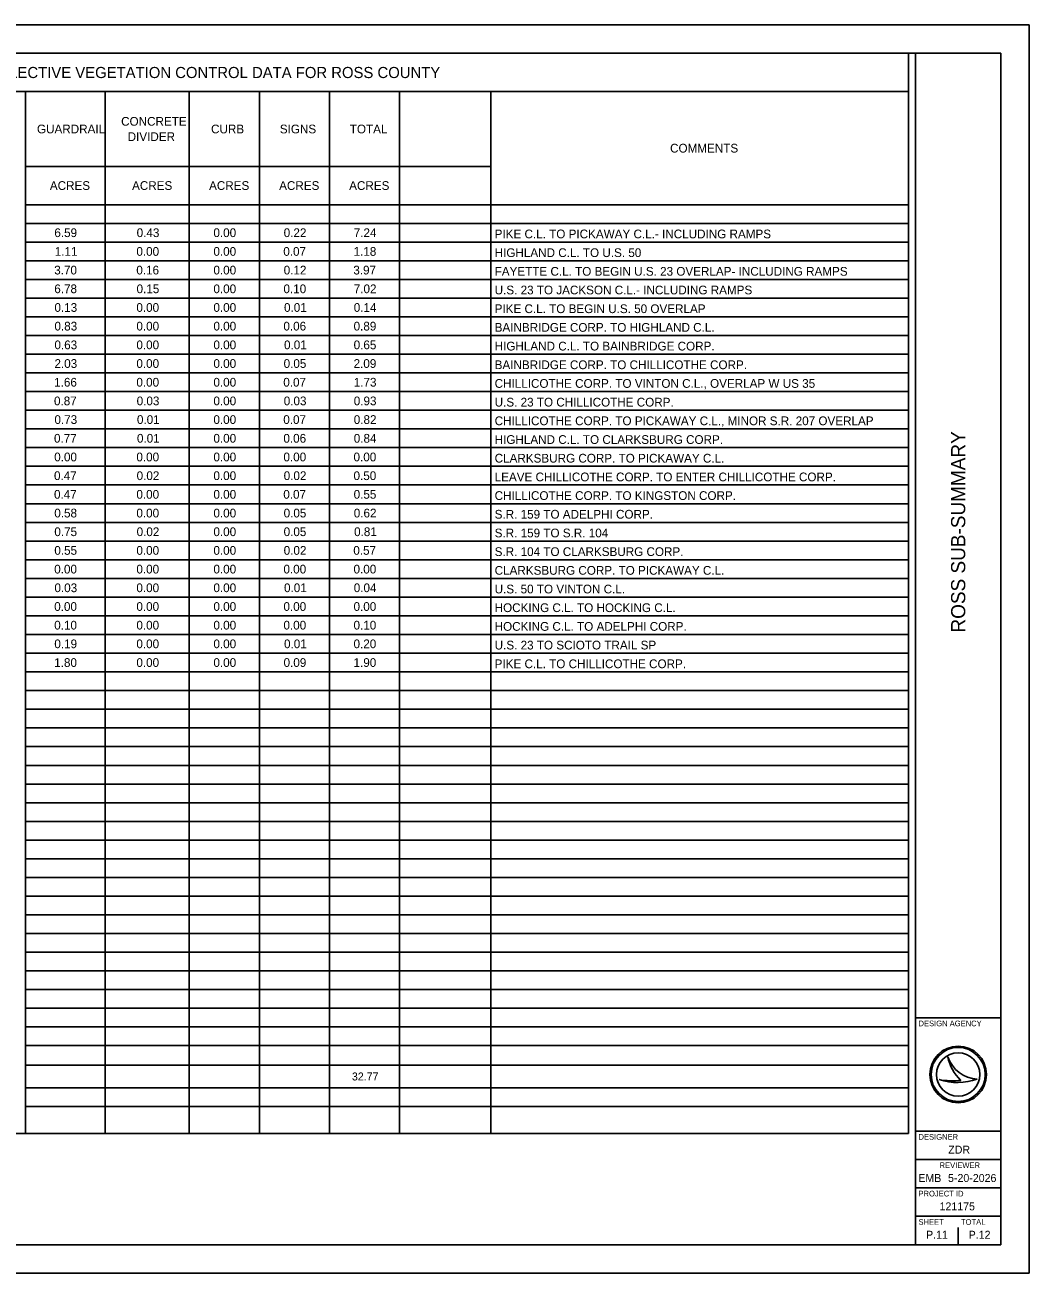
# Model space of a CAD drawing. Extents: x 0 to 34, y 0 to 22.
# Drawn here: x 16.29 to 34, y 0 to 22 of the extents above; entities that cross this region are included whole.
import ezdxf

# ---------------------------------------------------------------- set-up
doc = ezdxf.new("R2010")
doc.units = 0
for name, color, linetype in [('SH_Border', 7, 'Continuous'), ('SH_Cut_Line', 7, 'Continuous'), ('SH_Data', 7, 'Continuous'), ('SH_Text', 7, 'Continuous')]:
    doc.layers.add(name, color=color, linetype=linetype)

msp = doc.modelspace()

# ---------------------------------------------------------------- linework, layer by layer
at = {"layer": 'SH_Border'}
for p, q in [((32, 0.5), (32, 21.5)), ((32, 4.5), (33.5, 4.5)), ((32, 2.5), (33.5, 2.5)), ((32, 2), (33.5, 2)), ((32, 1.5), (33.5, 1.5)), ((32, 1), (33.5, 1))]:
    msp.add_line(p, q, dxfattribs=at)
msp.add_lwpolyline([(1.5, 21.5), (33.5, 21.5), (33.5, 0.5), (1.5, 0.5)], close=True, dxfattribs=at)
at = {"layer": 'SH_Cut_Line'}
msp.add_lwpolyline([(0, 0), (34, 0), (34, 22), (0, 22)], close=True, dxfattribs=at)
at = {"layer": 'SH_Data'}
for p, q in [((32.567, 3.81), (32.567, 3.81)), ((32.417, 3.41), (32.417, 3.41)), ((32.75, 3.5), (32.75, 3.5)), ((33.087, 3.419), (33.087, 3.419)), ((32.375, 0.675), (32.375, 0.675)), ((32.75, 0.5), (32.75, 0.8))]:
    msp.add_line(p, q, dxfattribs=at)
for radius in [0.5, 0.477, 0.477, 0.382]:
    msp.add_circle((32.75, 3.5), radius, dxfattribs=at)
for centre, radius, start, end in [((33.116, 3.998), 0.58, 198.9257, 198.9319), ((33.347, 3.97), 0.796, 191.6379, 191.6421), ((33.116, 3.998), 0.58, 198.9319, 267.1657), ((33.347, 3.97), 0.796, 191.6421, 226.0947), ((32.739, 4.37), 1.013, 251.4576, 290.0832), ((32.648, 4.654), 1.266, 259.4964, 259.4995), ((32.739, 4.37), 1.013, 251.4527, 251.4576), ((32.648, 4.654), 1.266, 259.4995, 276.6672)]:
    msp.add_arc(centre, radius, start, end, dxfattribs=at)
at = {"layer": 'SH_Text'}
for p, q in [((1.5, 21.5), (31.872, 21.5)), ((31.872, 21.5), (31.872, 2.46)), ((7.451, 20.825), (16.302, 20.825)), ((16.28, 20.825), (31.872, 20.825)), ((16.302, 20.825), (16.302, 2.46)), ((17.707, 20.825), (17.707, 2.46)), ((19.189, 20.825), (19.189, 2.46)), ((20.425, 20.825), (20.425, 2.46)), ((21.66, 20.825), (21.66, 2.46)), ((22.895, 20.825), (22.895, 2.46)), ((24.509, 20.825), (24.509, 2.46)), ((16.302, 19.507), (24.509, 19.507)), ((16.302, 18.832), (31.872, 18.832)), ((16.302, 18.502), (31.872, 18.502)), ((16.302, 18.173), (31.872, 18.173)), ((16.302, 17.844), (31.872, 17.844)), ((16.302, 17.514), (31.872, 17.514)), ((16.302, 17.185), (31.872, 17.185)), ((16.302, 16.855), (31.872, 16.855)), ((16.302, 16.526), (31.872, 16.526)), ((16.302, 16.196), (31.872, 16.196)), ((16.302, 15.867), (31.872, 15.867)), ((16.302, 15.538), (31.872, 15.538)), ((16.302, 15.208), (31.872, 15.208)), ((16.302, 14.879), (31.872, 14.879)), ((16.302, 14.549), (31.872, 14.549)), ((16.302, 14.22), (31.872, 14.22)), ((16.302, 13.891), (31.872, 13.891)), ((16.302, 13.561), (31.872, 13.561)), ((16.302, 13.232), (31.872, 13.232)), ((16.302, 12.902), (31.872, 12.902)), ((16.302, 12.573), (31.872, 12.573)), ((16.302, 12.244), (31.872, 12.244)), ((16.302, 11.914), (31.872, 11.914)), ((16.302, 11.585), (31.872, 11.585)), ((16.302, 11.255), (31.872, 11.255)), ((16.302, 10.926), (31.872, 10.926)), ((16.302, 10.596), (31.872, 10.596)), ((16.302, 10.267), (31.872, 10.267)), ((16.302, 9.938), (31.872, 9.938)), ((16.302, 9.608), (31.872, 9.608)), ((16.302, 9.279), (31.872, 9.279)), ((16.302, 8.949), (31.872, 8.949)), ((16.302, 8.62), (31.872, 8.62)), ((16.302, 8.291), (31.872, 8.291)), ((16.302, 7.961), (31.872, 7.961)), ((16.302, 7.632), (31.872, 7.632)), ((16.302, 7.302), (31.872, 7.302)), ((16.302, 6.973), (31.872, 6.973)), ((16.302, 6.644), (31.872, 6.644)), ((16.302, 6.314), (31.872, 6.314)), ((16.302, 5.985), (31.872, 5.985)), ((16.302, 5.655), (31.872, 5.655)), ((16.302, 5.326), (31.872, 5.326)), ((16.302, 4.996), (31.872, 4.996)), ((16.302, 4.667), (31.872, 4.667)), ((16.302, 4.338), (31.872, 4.338)), ((16.302, 4.008), (31.872, 4.008)), ((16.302, 3.662), (31.872, 3.662)), ((16.302, 3.267), (31.872, 3.267)), ((16.302, 2.938), (31.872, 2.938)), ((7.451, 2.46), (16.302, 2.46)), ((16.28, 2.46), (31.872, 2.46))]:
    msp.add_line(p, q, dxfattribs=at)

# ---------------------------------------------------------------- texts
at = {"layer": 'SH_Data'}
msp.add_text('ROSS SUB-SUMMARY', height=0.25, rotation=90, dxfattribs=at).set_placement((32.875, 11.29))
for s, height, p in [('DESIGN AGENCY', 0.1, (32.05, 4.35)), ('DESIGNER', 0.1, (32.05, 2.35)), ('ZDR', 0.14, (32.575, 2.105)), ('REVIEWER', 0.1, (32.422, 1.85)), ('EMB', 0.14, (32.047, 1.605)), ('5-20-2026', 0.14, (32.571, 1.605)), ('PROJECT ID', 0.1, (32.05, 1.35)), ('121175', 0.14, (32.421, 1.105)), ('SHEET', 0.1, (32.05, 0.85)), ('TOTAL', 0.1, (32.8, 0.85)), ('P.11', 0.14, (32.184, 0.605)), ('P.12', 0.14, (32.935, 0.605))]:
    msp.add_text(s, height=height, dxfattribs=at).set_placement(p)
at = {"layer": 'SH_Text'}
for s, height, p in [('HERBICIDAL SPRAYING NONSELECTIVE VEGETATION CONTROL DATA FOR ROSS COUNTY', 0.196, (12.008, 21.064)), ('GUARDRAIL', 0.154, (16.503, 20.089)), ('CONCRETE', 0.154, (17.987, 20.224)), ('CURB', 0.154, (19.573, 20.089)), ('SIGNS', 0.154, (20.786, 20.089)), ('TOTAL', 0.154, (22.02, 20.089)), ('DIVIDER', 0.154, (18.102, 19.954)), ('COMMENTS', 0.154, (27.669, 19.751)), ('ACRES', 0.154, (16.73, 19.092)), ('ACRES', 0.154, (18.18, 19.092)), ('ACRES', 0.154, (19.538, 19.092)), ('ACRES', 0.154, (20.774, 19.092)), ('ACRES', 0.154, (22.009, 19.092)), ('6.59', 0.154, (16.809, 18.261)), ('0.43', 0.154, (18.261, 18.261)), ('0.00', 0.154, (19.615, 18.261)), ('0.22', 0.154, (20.854, 18.261)), ('7.24', 0.154, (22.09, 18.261)), ('PIKE C.L. TO PICKAWAY C.L.- INCLUDING RAMPS', 0.154, (24.575, 18.239)), ('1.11', 0.154, (16.817, 17.931)), ('0.00', 0.154, (18.256, 17.931)), ('0.00', 0.154, (19.615, 17.931)), ('0.07', 0.154, (20.847, 17.931)), ('1.18', 0.154, (22.087, 17.931)), ('HIGHLAND C.L. TO U.S. 50', 0.154, (24.575, 17.909)), ('3.70', 0.154, (16.807, 17.602)), ('0.16', 0.154, (18.255, 17.602)), ('0.00', 0.154, (19.615, 17.602)), ('0.12', 0.154, (20.854, 17.602)), ('3.97', 0.154, (22.082, 17.602)), ('FAYETTE C.L. TO BEGIN U.S. 23 OVERLAP- INCLUDING RAMPS', 0.154, (24.575, 17.58)), ('6.78', 0.154, (16.808, 17.272)), ('0.15', 0.154, (18.259, 17.272)), ('0.00', 0.154, (19.615, 17.272)), ('0.10', 0.154, (20.85, 17.272)), ('7.02', 0.154, (22.09, 17.272)), ('U.S. 23 TO JACKSON C.L.- INCLUDING RAMPS', 0.154, (24.575, 17.251)), ('0.13', 0.154, (16.811, 16.943)), ('0.00', 0.154, (18.256, 16.943)), ('0.00', 0.154, (19.615, 16.943)), ('0.01', 0.154, (20.86, 16.943)), ('0.14', 0.154, (22.09, 16.943)), ('PIKE C.L. TO BEGIN U.S. 50 OVERLAP', 0.154, (24.575, 16.921)), ('0.83', 0.154, (16.811, 16.614)), ('0.00', 0.154, (18.256, 16.614)), ('0.00', 0.154, (19.615, 16.614)), ('0.06', 0.154, (20.849, 16.614)), ('0.89', 0.154, (22.087, 16.614)), ('BAINBRIDGE CORP. TO HIGHLAND C.L.', 0.154, (24.575, 16.592)), ('0.63', 0.154, (16.811, 16.284)), ('0.00', 0.154, (18.256, 16.284)), ('0.00', 0.154, (19.615, 16.284)), ('0.01', 0.154, (20.86, 16.284)), ('0.65', 0.154, (22.088, 16.284)), ('HIGHLAND C.L. TO BAINBRIDGE CORP.', 0.154, (24.575, 16.262)), ('2.03', 0.154, (16.811, 15.955)), ('0.00', 0.154, (18.256, 15.955)), ('0.00', 0.154, (19.615, 15.955)), ('0.05', 0.154, (20.853, 15.955)), ('2.09', 0.154, (22.087, 15.955)), ('BAINBRIDGE CORP. TO CHILLICOTHE CORP.', 0.154, (24.575, 15.933)), ('1.66', 0.154, (16.806, 15.625)), ('0.00', 0.154, (18.256, 15.625)), ('0.00', 0.154, (19.615, 15.625)), ('0.07', 0.154, (20.847, 15.625)), ('1.73', 0.154, (22.09, 15.625)), ('CHILLICOTHE CORP. TO VINTON C.L., OVERLAP W US 35', 0.154, (24.575, 15.604)), ('0.87', 0.154, (16.803, 15.296)), ('0.03', 0.154, (18.261, 15.296)), ('0.00', 0.154, (19.615, 15.296)), ('0.03', 0.154, (20.855, 15.296)), ('0.93', 0.154, (22.09, 15.296)), ('U.S. 23 TO CHILLICOTHE CORP.', 0.154, (24.575, 15.274)), ('0.73', 0.154, (16.811, 14.967)), ('0.01', 0.154, (18.266, 14.967)), ('0.00', 0.154, (19.615, 14.967)), ('0.07', 0.154, (20.847, 14.967)), ('0.82', 0.154, (22.09, 14.967)), ('CHILLICOTHE CORP. TO PICKAWAY C.L., MINOR S.R. 207 OVERLAP', 0.154, (24.575, 14.945)), ('0.77', 0.154, (16.803, 14.637)), ('0.01', 0.154, (18.266, 14.637)), ('0.00', 0.154, (19.615, 14.637)), ('0.06', 0.154, (20.849, 14.637)), ('0.84', 0.154, (22.09, 14.637)), ('HIGHLAND C.L. TO CLARKSBURG CORP.', 0.154, (24.575, 14.615)), ('0.00', 0.154, (16.807, 14.308)), ('0.00', 0.154, (18.256, 14.308)), ('0.00', 0.154, (19.615, 14.308)), ('0.00', 0.154, (20.85, 14.308)), ('0.00', 0.154, (22.086, 14.308)), ('CLARKSBURG CORP. TO PICKAWAY C.L.', 0.154, (24.575, 14.286)), ('0.47', 0.154, (16.803, 13.978)), ('0.02', 0.154, (18.26, 13.978)), ('0.00', 0.154, (19.615, 13.978)), ('0.02', 0.154, (20.854, 13.978)), ('0.50', 0.154, (22.086, 13.978)), ('LEAVE CHILLICOTHE CORP. TO ENTER CHILLICOTHE CORP.', 0.154, (24.575, 13.956)), ('0.47', 0.154, (16.803, 13.649)), ('0.00', 0.154, (18.256, 13.649)), ('0.00', 0.154, (19.615, 13.649)), ('0.07', 0.154, (20.847, 13.649)), ('0.55', 0.154, (22.088, 13.649)), ('CHILLICOTHE CORP. TO KINGSTON CORP.', 0.154, (24.575, 13.627)), ('0.58', 0.154, (16.808, 13.319)), ('0.00', 0.154, (18.256, 13.319)), ('0.00', 0.154, (19.615, 13.319)), ('0.05', 0.154, (20.853, 13.319)), ('0.62', 0.154, (22.09, 13.319)), ('S.R. 159 TO ADELPHI CORP.', 0.154, (24.575, 13.298)), ('0.75', 0.154, (16.809, 12.99)), ('0.02', 0.154, (18.26, 12.99)), ('0.00', 0.154, (19.615, 12.99)), ('0.05', 0.154, (20.853, 12.99)), ('0.81', 0.154, (22.096, 12.99)), ('S.R. 159 TO S.R. 104', 0.154, (24.575, 12.968)), ('0.55', 0.154, (16.809, 12.661)), ('0.00', 0.154, (18.256, 12.661)), ('0.00', 0.154, (19.615, 12.661)), ('0.02', 0.154, (20.854, 12.661)), ('0.57', 0.154, (22.082, 12.661)), ('S.R. 104 TO CLARKSBURG CORP.', 0.154, (24.575, 12.639)), ('0.00', 0.154, (16.807, 12.331)), ('0.00', 0.154, (18.256, 12.331)), ('0.00', 0.154, (19.615, 12.331)), ('0.00', 0.154, (20.85, 12.331)), ('0.00', 0.154, (22.086, 12.331)), ('CLARKSBURG CORP. TO PICKAWAY C.L.', 0.154, (24.575, 12.309)), ('0.03', 0.154, (16.811, 12.002)), ('0.00', 0.154, (18.256, 12.002)), ('0.00', 0.154, (19.615, 12.002)), ('0.01', 0.154, (20.86, 12.002)), ('0.04', 0.154, (22.09, 12.002)), ('U.S. 50 TO VINTON C.L.', 0.154, (24.575, 11.98)), ('0.00', 0.154, (16.807, 11.672)), ('0.00', 0.154, (18.256, 11.672)), ('0.00', 0.154, (19.615, 11.672)), ('0.00', 0.154, (20.85, 11.672)), ('0.00', 0.154, (22.086, 11.672)), ('HOCKING C.L. TO HOCKING C.L.', 0.154, (24.575, 11.651)), ('0.10', 0.154, (16.807, 11.343)), ('0.00', 0.154, (18.256, 11.343)), ('0.00', 0.154, (19.615, 11.343)), ('0.00', 0.154, (20.85, 11.343)), ('0.10', 0.154, (22.086, 11.343)), ('HOCKING C.L. TO ADELPHI CORP.', 0.154, (24.575, 11.321)), ('0.19', 0.154, (16.809, 11.014)), ('0.00', 0.154, (18.256, 11.014)), ('0.00', 0.154, (19.615, 11.014)), ('0.01', 0.154, (20.86, 11.014)), ('0.20', 0.154, (22.086, 11.014)), ('U.S. 23 TO SCIOTO TRAIL SP', 0.154, (24.575, 10.992)), ('1.80', 0.154, (16.807, 10.684)), ('0.00', 0.154, (18.256, 10.684)), ('0.00', 0.154, (19.615, 10.684)), ('0.09', 0.154, (20.852, 10.684)), ('1.90', 0.154, (22.086, 10.684)), ('PIKE C.L. TO CHILLICOTHE CORP.', 0.154, (24.575, 10.662)), ('32.77', 0.14, (22.057, 3.395))]:
    msp.add_text(s, height=height, dxfattribs=at).set_placement(p)

doc.saveas('drawing.dxf')
